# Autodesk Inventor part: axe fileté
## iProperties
Created: 2002-05
Part Number: axe fileté
Material: Par défaut
Document SubType Name: Modélisation
Designer: REVEST Pierre
Control State: 0
Master: False
Checked Out: False
Shininess: 25.0
Length Units: 11269
Angle Units: 11279
Time Units: 11290
Mass Units: 11283
Length Display Precision: 3
Angle Display Precision: 2
Density: 0.0
Volumn: 0.0
Area: 0.0
PropertySet Name: Model Information
Author: REVEST Pierre
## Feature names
1. Extrusion1
2. Chanfrein1 [Chamfer]
